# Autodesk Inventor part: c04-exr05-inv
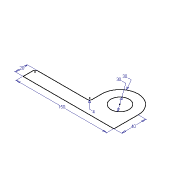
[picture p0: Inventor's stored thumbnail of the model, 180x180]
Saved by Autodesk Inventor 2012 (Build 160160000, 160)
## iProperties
Shininess: 64.0
Length Units: 11269
Angle Units: 11279
Time Units: 11290
Mass Units: 11283
Length Display Precision: 3
Angle Display Precision: 2
Compacted: True
Created: 2002-02
Part Number: c04-exr05-inv
Document SubType Name: Modeling
Density: 1 g/cm^3
Material: Default
Density: 0.0
Volumn: 0.0
Area: 0.0
PropertySet Name: Model Information
Control State: 0
Master: False
Checked Out: False
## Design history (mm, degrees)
sketch "Sketch1"
  geometry: L1 (-66.957, -29.14)-(83.043, -29.14); L2 (83.043, -29.14)-(83.043, 10.86); L3 (23.043, 10.86)-(23.043, -5.14); L4 (19.043, -9.14)-(-62.957, -9.14); L5 (-66.957, -13.14)-(-66.957, -29.14); C1 r 15 at (53.043, 10.86); A1 r 30 centre (53.043, 10.86) between (83.043, 10.86) and (23.043, 10.86); A2 r 4 centre (19.043, -5.14) between (19.043, -9.14) and (23.043, -5.14); A3 r 4 centre (-62.957, -13.14) between (-62.957, -9.14) and (-66.957, -13.14)
  constraints: 10 end point, 6 point on circle, 6 tangent, 4 centre point, 3 parallel, 1 coincident, 1 equal radius, 1 horizontal, 1 perpendicular
  dimensions: "d0" = 150 distance of L1.start L1.end; "d1" = 40 distance of L1.end L2.end; "d2" = 30 radius of A1; "d4" = 4 radius of A2; "d5" = 20 distance between parallel lines of L1 L4; "d6" = 30 diameter of C1
